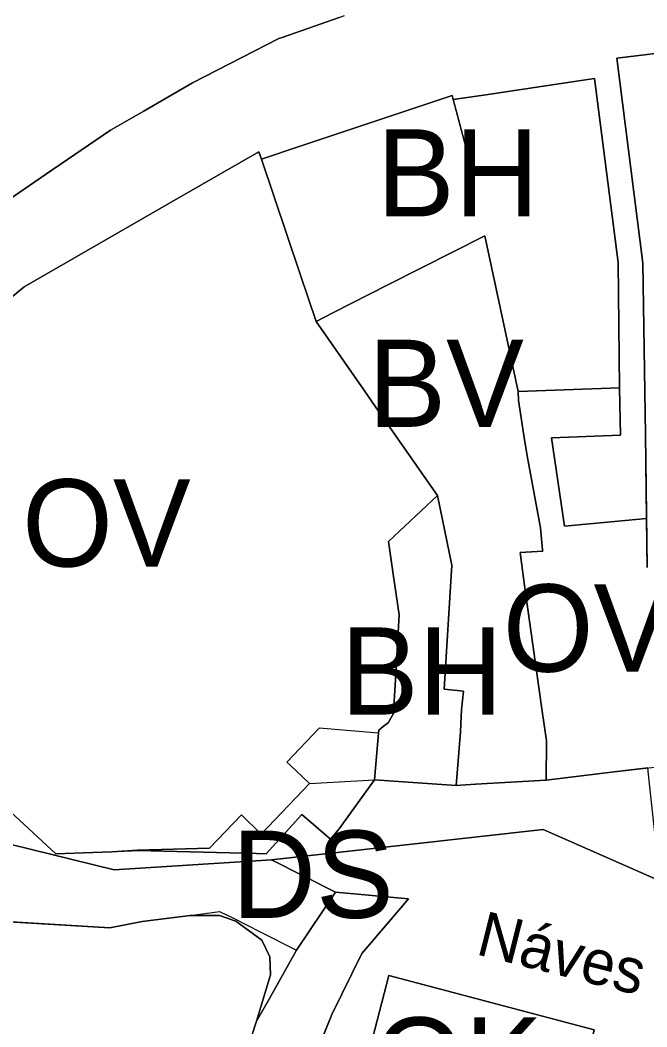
# Model space of a CAD drawing. Extents: x -555509 to -553005, y -1186756 to -1182560.
# Drawn here: x -554552.4 to -554451.9, y -1184542.3 to -1184380.7 of the extents above; entities that cross this region are included whole.
import ezdxf

# ---------------------------------------------------------------- set-up
doc = ezdxf.new("R2010")
doc.units = 0
for name, color, linetype in [('Level 15', 7, 'Continuous'), ('Level 48', 7, 'Continuous'), ('Level 57', 7, 'Continuous'), ('Level 59', 7, 'Continuous'), ('OBRYS_PLOCH', 7, 'Continuous'), ('stav_BV', 7, 'Continuous'), ('stav_DS', 7, 'Continuous'), ('stav_OK', 7, 'Continuous'), ('stav_OV', 7, 'Continuous'), ('stav_PU', 7, 'Continuous'), ('stav_ZP', 7, 'Continuous')]:
    doc.layers.add(name, color=color, linetype=linetype)

msp = doc.modelspace()

# ---------------------------------------------------------------- linework, layer by layer
at = {"layer": 'Level 15'}
for points in [[(-554501.25, -1184380.29), (-554510.4, -1184383.49), (-554510.93, -1184383.67), (-554516.84, -1184386.71), (-554524.77, -1184390.79), (-554532.69, -1184395.37), (-554537.96, -1184398.36), (-554548.38, -1184405.51), (-554555.22, -1184410.2), (-554562.77, -1184415.14), (-554568.86, -1184419.58), (-554572.85, -1184422.48), (-554590.45, -1184437.03), (-554601.65, -1184446.29), (-554608.34, -1184451.84), (-554612.7, -1184455.49), (-554618.09, -1184459.82), (-554614.87, -1184465.98), (-554617.55, -1184467.95), (-554620.8, -1184470.08), (-554622.34, -1184471.17), (-554623.12, -1184469.96), (-554625.1, -1184471.14), (-554624.26, -1184472.46)], [(-554465.07, -1184461.92), (-554451.93, -1184460.67), (-554452.12, -1184447.23), (-554452.51, -1184419.74), (-554456.69, -1184386.82), (-554441.64, -1184385.02)], [(-554555.44, -1184426.5), (-554551.78, -1184423.5), (-554526.46, -1184408.92), (-554526.07, -1184408.7), (-554514.13, -1184401.83), (-554513.72, -1184403.03), (-554507.68, -1184401.01), (-554492.26, -1184395.86), (-554483.13, -1184392.82), (-554482.96, -1184393.47), (-554477.73, -1184392.69), (-554463.86, -1184390.62), (-554460.27, -1184390.08), (-554457.65, -1184410.45), (-554456.48, -1184419.6), (-554456.27, -1184439.75), (-554456.1, -1184447.34), (-554467.17, -1184447.74), (-554465.07, -1184461.92)], [(-554661.22, -1184499.44), (-554615.47, -1184491.83), (-554615.39, -1184490.55), (-554604.27, -1184473.37), (-554583.45, -1184490.21), (-554587.32, -1184496), (-554576.02, -1184502.11), (-554572.02, -1184504.27), (-554564.98, -1184508.08), (-554557.42, -1184512.17), (-554537.36, -1184517.08), (-554512.11, -1184515.49), (-554468.49, -1184510.58), (-554431.8, -1184526.75)], [(-554495.6, -1184502.63), (-554494.94, -1184495.16), (-554504.44, -1184494.32), (-554509.62, -1184499.78), (-554509.18, -1184500.21), (-554506.01, -1184503.24), (-554513.76, -1184511.35), (-554516.89, -1184508.26), (-554522.03, -1184513.6), (-554533.6, -1184513.89), (-554536.89, -1184514.13)], [(-554451.72, -1184500.72), (-554457.1, -1184501.34), (-554457.1, -1184501.34), (-554468.05, -1184502.66), (-554479.39, -1184503.34), (-554482.49, -1184503.52), (-554495.6, -1184502.63), (-554501.22, -1184510.51), (-554502.66, -1184512.16), (-554507.24, -1184508.19), (-554512.95, -1184514.48), (-554514.52, -1184514.44), (-554529.44, -1184514.09), (-554533.44, -1184513.99), (-554536.89, -1184514.13), (-554537.7, -1184514.16), (-554540.78, -1184514.29), (-554546.69, -1184514.53), (-554560.62, -1184501.69)], [(-554622.88, -1184503.76), (-554615.1, -1184503.37), (-554607.58, -1184505.07), (-554591.92, -1184508.62), (-554588.8, -1184510.03), (-554562.63, -1184524.9), (-554538.03, -1184526.36), (-554532.88, -1184525.38), (-554525.17, -1184524.38), (-554520.44, -1184524.39), (-554517.85, -1184525.31), (-554513.65, -1184528.36), (-554512.36, -1184531.03), (-554512.28, -1184533.93), (-554514.53, -1184541.36)], [(-554502.66, -1184512.16), (-554501.22, -1184510.51), (-554495.6, -1184502.63)], [(-554512.11, -1184515.49), (-554537.36, -1184517.08), (-554557.42, -1184512.17), (-554564.98, -1184508.08)], [(-554536.89, -1184514.13), (-554533.44, -1184513.99), (-554529.44, -1184514.09), (-554514.52, -1184514.44), (-554512.95, -1184514.48), (-554507.24, -1184508.19), (-554502.66, -1184512.16)], [(-554431.8, -1184526.75), (-554468.49, -1184510.58), (-554512.11, -1184515.49), (-554501.82, -1184520.64), (-554490.14, -1184521.71), (-554496.01, -1184528.61), (-554497.62, -1184530.51), (-554502.44, -1184540.28), (-554503.73, -1184543.47), (-554500.65, -1184544.34), (-554499.87, -1184544.56), (-554496.29, -1184545.6), (-554493.28, -1184534.02), (-554460.33, -1184542.77), (-554461.09, -1184545.8), (-554464.39, -1184558.17), (-554462.1, -1184559.62), (-554456.48, -1184546.98), (-554454.18, -1184547.62), (-554450.06, -1184548.76)], [(-554514.53, -1184541.36), (-554512.46, -1184537.85), (-554508.08, -1184529.95), (-554501.82, -1184520.64), (-554512.11, -1184515.49)], [(-554501.82, -1184520.64), (-554508.08, -1184529.95), (-554512.46, -1184537.85), (-554514.53, -1184541.36)], [(-554503.73, -1184543.47), (-554502.44, -1184540.28), (-554497.62, -1184530.51), (-554496.01, -1184528.61), (-554490.14, -1184521.71), (-554501.82, -1184520.64)], [(-554514.53, -1184541.36), (-554523.93, -1184570.22), (-554534.86, -1184570.77), (-554558.65, -1184573.59), (-554586.8, -1184578.55), (-554589.05, -1184575.07)]]:
    msp.add_lwpolyline(points, dxfattribs=at)
at = {"layer": 'Level 48'}
for p, q in [((-554457.65, -1184410.45), (-554460.27, -1184390.08)), ((-554479.61, -1184406.08), (-554483.13, -1184392.82)), ((-554482.96, -1184393.47), (-554479.61, -1184406.08)), ((-554513.72, -1184403.03), (-554507.5, -1184421.48)), ((-554493.34, -1184423.13), (-554477.89, -1184415.35)), ((-554477.89, -1184415.35), (-554472.51, -1184440.32)), ((-554507.5, -1184421.48), (-554504.94, -1184429.06)), ((-554502.26, -1184427.69), (-554493.34, -1184423.13)), ((-554504.94, -1184429.06), (-554502.26, -1184427.69)), ((-554472.51, -1184440.32), (-554456.27, -1184439.75)), ((-554494.94, -1184495.16), (-554495.6, -1184502.63)), ((-554495.6, -1184502.63), (-554482.49, -1184503.52))]:
    msp.add_line(p, q, dxfattribs=at)
for points in [[(-554460.27, -1184390.08), (-554463.86, -1184390.62), (-554477.73, -1184392.69), (-554482.96, -1184393.47)], [(-554483.13, -1184392.82), (-554492.26, -1184395.86), (-554507.68, -1184401.01), (-554513.72, -1184403.03)], [(-554456.27, -1184439.75), (-554456.48, -1184419.6), (-554457.65, -1184410.45)], [(-554485.48, -1184457), (-554493.34, -1184464.37), (-554492.58, -1184469.63), (-554491.64, -1184476.13), (-554491.8, -1184478.94), (-554492.17, -1184485.75)], [(-554481.62, -1184491.37), (-554481.28, -1184488.38), (-554484.42, -1184488.1), (-554483.16, -1184468.16), (-554485.48, -1184457)], [(-554492.17, -1184485.75), (-554492.36, -1184489.12), (-554492.52, -1184491.97), (-554493.38, -1184493.48), (-554494.16, -1184494.08), (-554494.9, -1184494.65), (-554494.94, -1184495.16)], [(-554482.49, -1184503.52), (-554481.8, -1184494.9), (-554481.69, -1184492.44), (-554481.62, -1184491.37)]]:
    msp.add_lwpolyline(points, dxfattribs=at)
at = {"layer": 'OBRYS_PLOCH'}
for p, q in [((-554510.4, -1184383.49), (-554501.25, -1184380.29)), ((-554510.93, -1184383.67), (-554510.4, -1184383.49)), ((-554457.65, -1184410.45), (-554460.27, -1184390.08)), ((-554479.61, -1184406.08), (-554483.13, -1184392.82)), ((-554482.96, -1184393.47), (-554479.61, -1184406.08)), ((-554537.96, -1184398.36), (-554532.69, -1184395.37)), ((-554548.38, -1184405.51), (-554537.96, -1184398.36)), ((-554513.72, -1184403.03), (-554507.5, -1184421.48)), ((-554477.89, -1184415.35), (-554493.34, -1184423.13)), ((-554493.34, -1184423.13), (-554477.89, -1184415.35)), ((-554472.51, -1184440.32), (-554477.89, -1184415.35)), ((-554477.89, -1184415.35), (-554472.51, -1184440.32)), ((-554507.5, -1184421.48), (-554504.94, -1184429.06)), ((-554493.34, -1184423.13), (-554502.26, -1184427.69)), ((-554502.26, -1184427.69), (-554493.34, -1184423.13)), ((-554502.26, -1184427.69), (-554504.94, -1184429.06)), ((-554504.94, -1184429.06), (-554502.26, -1184427.69)), ((-554456.27, -1184439.75), (-554472.51, -1184440.32)), ((-554472.51, -1184440.32), (-554456.27, -1184439.75)), ((-554472.51, -1184440.32), (-554472.48, -1184441.75)), ((-554472.48, -1184441.75), (-554472.51, -1184440.32)), ((-554472.48, -1184441.75), (-554471.55, -1184447.68)), ((-554471.55, -1184447.68), (-554472.48, -1184441.75)), ((-554471.55, -1184447.68), (-554471.08, -1184450.66)), ((-554471.08, -1184450.66), (-554471.55, -1184447.68)), ((-554465.07, -1184461.92), (-554467.17, -1184447.74)), ((-554471.08, -1184450.66), (-554468.93, -1184462.21)), ((-554468.93, -1184462.21), (-554471.08, -1184450.66)), ((-554451.93, -1184460.67), (-554465.07, -1184461.92)), ((-554451.82, -1184468.57), (-554451.93, -1184460.67)), ((-554468.93, -1184462.21), (-554468.63, -1184465.74)), ((-554468.63, -1184465.74), (-554468.93, -1184462.21)), ((-554495.6, -1184502.63), (-554494.94, -1184495.16)), ((-554494.94, -1184495.16), (-554495.6, -1184502.63)), ((-554506.01, -1184503.24), (-554495.6, -1184502.63)), ((-554495.6, -1184502.63), (-554482.49, -1184503.52)), ((-554537.36, -1184517.08), (-554557.42, -1184512.17)), ((-554512.11, -1184515.49), (-554537.36, -1184517.08)), ((-554501.82, -1184520.64), (-554512.11, -1184515.49)), ((-554501.82, -1184520.64), (-554501.82, -1184520.64)), ((-554562.63, -1184524.9), (-554538.03, -1184526.36)), ((-554525.17, -1184524.38), (-554520.43, -1184523.77)), ((-554525.17, -1184524.38), (-554525.17, -1184524.38)), ((-554520.43, -1184523.77), (-554518.09, -1184524.86)), ((-554518.09, -1184524.86), (-554513.9, -1184527.03)), ((-554513.9, -1184527.03), (-554508.08, -1184529.95)), ((-554502.44, -1184540.28), (-554497.62, -1184530.51)), ((-554512.46, -1184537.85), (-554514.53, -1184541.36)), ((-554503.73, -1184543.47), (-554502.44, -1184540.28)), ((-554514.53, -1184541.36), (-554523.93, -1184570.22))]:
    msp.add_line(p, q, dxfattribs=at)
for points in [[(-554532.69, -1184395.37), (-554524.77, -1184390.79), (-554516.84, -1184386.71), (-554510.93, -1184383.67)], [(-554441.64, -1184385.02), (-554456.69, -1184386.82), (-554452.51, -1184419.74), (-554452.12, -1184447.23), (-554451.82, -1184468.57)], [(-554460.27, -1184390.08), (-554463.86, -1184390.62), (-554477.73, -1184392.69), (-554482.96, -1184393.47)], [(-554483.13, -1184392.82), (-554492.26, -1184395.86), (-554507.68, -1184401.01), (-554513.72, -1184403.03)], [(-554494.94, -1184495.16), (-554494.9, -1184494.65), (-554494.16, -1184494.08), (-554493.38, -1184493.48), (-554492.52, -1184491.97), (-554492.36, -1184489.12), (-554492.17, -1184485.75), (-554491.8, -1184478.94), (-554491.64, -1184476.13), (-554492.58, -1184469.63), (-554493.34, -1184464.37), (-554485.48, -1184457), (-554485.74, -1184456.63), (-554495.39, -1184442.77), (-554497.29, -1184440.04), (-554504.94, -1184429.06), (-554507.5, -1184421.48), (-554513.72, -1184403.03), (-554514.13, -1184401.83), (-554526.07, -1184408.7), (-554526.46, -1184408.92), (-554551.78, -1184423.5), (-554555.44, -1184426.5)], [(-554562.77, -1184415.14), (-554555.22, -1184410.2), (-554548.38, -1184405.51)], [(-554456.27, -1184439.75), (-554456.48, -1184419.6), (-554457.65, -1184410.45)], [(-554504.94, -1184429.06), (-554497.29, -1184440.04), (-554495.39, -1184442.77), (-554485.74, -1184456.63), (-554485.48, -1184457), (-554483.16, -1184468.16), (-554484.42, -1184488.1), (-554481.28, -1184488.38), (-554481.62, -1184491.37)], [(-554467.17, -1184447.74), (-554456.1, -1184447.34), (-554456.27, -1184439.75)], [(-554485.48, -1184457), (-554493.34, -1184464.37), (-554492.58, -1184469.63), (-554491.64, -1184476.13), (-554491.8, -1184478.94), (-554492.17, -1184485.75)], [(-554481.62, -1184491.37), (-554481.28, -1184488.38), (-554484.42, -1184488.1), (-554483.16, -1184468.16), (-554485.48, -1184457)], [(-554468.63, -1184465.74), (-554468.55, -1184465.93), (-554472.2, -1184466.16), (-554471.52, -1184471.45), (-554468.72, -1184491.22)], [(-554468.72, -1184491.22), (-554471.52, -1184471.45), (-554472.2, -1184466.16), (-554468.55, -1184465.93), (-554468.63, -1184465.74)], [(-554492.17, -1184485.75), (-554492.36, -1184489.12), (-554492.52, -1184491.97), (-554493.38, -1184493.48), (-554494.16, -1184494.08), (-554494.9, -1184494.65), (-554494.94, -1184495.16)], [(-554481.62, -1184491.37), (-554481.69, -1184492.44), (-554481.8, -1184494.9), (-554482.49, -1184503.52)], [(-554482.49, -1184503.52), (-554481.8, -1184494.9), (-554481.69, -1184492.44), (-554481.62, -1184491.37)], [(-554468.72, -1184491.22), (-554468, -1184496.38), (-554468.05, -1184502.66)], [(-554468.05, -1184502.66), (-554468, -1184496.38), (-554468.72, -1184491.22)], [(-554468.05, -1184502.66), (-554457.1, -1184501.34), (-554439.89, -1184499.37)], [(-554560.62, -1184501.69), (-554546.69, -1184514.53), (-554540.78, -1184514.29), (-554537.7, -1184514.16), (-554536.89, -1184514.13), (-554533.6, -1184513.89), (-554522.03, -1184513.6), (-554516.89, -1184508.26), (-554513.76, -1184511.35), (-554506.01, -1184503.24)], [(-554589.05, -1184575.07), (-554586.8, -1184578.55), (-554558.65, -1184573.59), (-554534.86, -1184570.77), (-554523.93, -1184570.22), (-554514.53, -1184541.36), (-554512.28, -1184533.93), (-554512.36, -1184531.03), (-554513.65, -1184528.36), (-554517.85, -1184525.31), (-554520.44, -1184524.39), (-554525.17, -1184524.38), (-554532.88, -1184525.38), (-554538.03, -1184526.36), (-554562.63, -1184524.9), (-554588.8, -1184510.03), (-554591.92, -1184508.62), (-554607.58, -1184505.07), (-554615.1, -1184503.37), (-554622.88, -1184503.76)], [(-554482.49, -1184503.52), (-554479.39, -1184503.34), (-554468.05, -1184502.66)], [(-554497.62, -1184530.51), (-554496.01, -1184528.61), (-554490.14, -1184521.71), (-554501.82, -1184520.64)], [(-554538.03, -1184526.36), (-554532.88, -1184525.38), (-554525.17, -1184524.38)], [(-554508.08, -1184529.95), (-554512.46, -1184537.85)]]:
    msp.add_lwpolyline(points, dxfattribs=at)
msp.add_lwpolyline([(-554490.82, -1184563.58), (-554486.05, -1184560.65), (-554484.65, -1184558.85), (-554470.11, -1184562.71), (-554469.92, -1184562.02), (-554469.15, -1184562.23), (-554468.04, -1184558.05), (-554468.82, -1184557.84), (-554468.61, -1184557.07), (-554464.39, -1184558.17), (-554461.09, -1184545.8), (-554460.33, -1184542.77), (-554493.28, -1184534.02), (-554496.29, -1184545.6), (-554499.87, -1184544.56), (-554500.65, -1184544.34), (-554501.53, -1184547.4), (-554501.31, -1184547.46), (-554502.51, -1184549.89), (-554505.11, -1184548.62), (-554508.55, -1184556.13), (-554503.03, -1184558.71)], close=True, dxfattribs=at)
at = {"layer": 'stav_BV'}
for p, q in [((-554516.84, -1184386.71), (-554510.93, -1184383.67)), ((-554477.89, -1184415.35), (-554493.34, -1184423.13)), ((-554472.51, -1184440.32), (-554477.89, -1184415.35)), ((-554493.34, -1184423.13), (-554502.26, -1184427.69)), ((-554502.26, -1184427.69), (-554504.94, -1184429.06)), ((-554472.48, -1184441.75), (-554472.51, -1184440.32)), ((-554471.55, -1184447.68), (-554472.48, -1184441.75)), ((-554471.08, -1184450.66), (-554471.55, -1184447.68)), ((-554468.93, -1184462.21), (-554471.08, -1184450.66)), ((-554468.63, -1184465.74), (-554468.93, -1184462.21))]:
    msp.add_line(p, q, dxfattribs=at)
for points in [[(-554510.93, -1184383.67), (-554510.4, -1184383.49), (-554501.25, -1184380.29), (-554500.4, -1184379.99)], [(-554441.64, -1184385.02), (-554456.69, -1184386.82), (-554452.51, -1184419.74), (-554452.12, -1184447.23), (-554451.82, -1184468.57)], [(-554532.69, -1184395.37), (-554524.77, -1184390.79), (-554516.84, -1184386.71)], [(-554555.22, -1184410.2), (-554548.38, -1184405.51), (-554537.96, -1184398.36), (-554532.69, -1184395.37)], [(-554504.94, -1184429.06), (-554497.29, -1184440.04), (-554495.39, -1184442.77), (-554485.74, -1184456.63), (-554485.48, -1184457), (-554483.16, -1184468.16), (-554484.42, -1184488.1), (-554481.28, -1184488.38), (-554481.62, -1184491.37)], [(-554468.72, -1184491.22), (-554471.52, -1184471.45), (-554472.2, -1184466.16), (-554468.55, -1184465.93), (-554468.63, -1184465.74)], [(-554481.62, -1184491.37), (-554481.69, -1184492.44), (-554481.8, -1184494.9), (-554482.49, -1184503.52)], [(-554468.05, -1184502.66), (-554468, -1184496.38), (-554468.72, -1184491.22)], [(-554482.49, -1184503.52), (-554479.39, -1184503.34), (-554468.05, -1184502.66)]]:
    msp.add_lwpolyline(points, dxfattribs=at)
at = {"layer": 'stav_DS'}
for p, q in [((-554537.36, -1184517.08), (-554557.42, -1184512.17)), ((-554512.11, -1184515.49), (-554537.36, -1184517.08)), ((-554501.82, -1184520.64), (-554512.11, -1184515.49)), ((-554490.14, -1184521.71), (-554501.82, -1184520.64)), ((-554496.01, -1184528.61), (-554490.14, -1184521.71)), ((-554525.17, -1184524.38), (-554520.43, -1184523.77)), ((-554520.43, -1184523.77), (-554518.09, -1184524.86)), ((-554518.09, -1184524.86), (-554513.9, -1184527.03)), ((-554513.9, -1184527.03), (-554508.08, -1184529.95)), ((-554497.62, -1184530.51), (-554496.01, -1184528.61)), ((-554508.08, -1184529.95), (-554512.46, -1184537.85)), ((-554502.44, -1184540.28), (-554497.62, -1184530.51)), ((-554512.46, -1184537.85), (-554514.53, -1184541.36)), ((-554505.72, -1184548.39), (-554502.44, -1184540.28))]:
    msp.add_line(p, q, dxfattribs=at)
for points in [[(-554588.8, -1184510.03), (-554562.63, -1184524.9), (-554538.03, -1184526.36), (-554532.88, -1184525.38), (-554525.17, -1184524.38), (-554525.17, -1184524.38)], [(-554514.53, -1184541.36), (-554523.93, -1184570.22), (-554523.93, -1184570.22)]]:
    msp.add_lwpolyline(points, dxfattribs=at)
at = {"layer": 'stav_OK'}
msp.add_lwpolyline([(-554490.82, -1184563.58), (-554486.05, -1184560.65), (-554484.65, -1184558.85), (-554470.11, -1184562.71), (-554469.92, -1184562.02), (-554469.15, -1184562.23), (-554468.04, -1184558.05), (-554468.82, -1184557.84), (-554468.61, -1184557.07), (-554464.39, -1184558.17), (-554461.09, -1184545.8), (-554460.33, -1184542.77), (-554493.28, -1184534.02), (-554496.29, -1184545.6), (-554499.87, -1184544.56), (-554500.65, -1184544.34), (-554501.53, -1184547.4), (-554501.31, -1184547.46), (-554502.51, -1184549.89), (-554505.11, -1184548.62), (-554508.55, -1184556.13), (-554503.03, -1184558.71)], close=True, dxfattribs=at)
at = {"layer": 'stav_OV'}
for p, q in [((-554456.27, -1184439.75), (-554472.51, -1184440.32)), ((-554472.51, -1184440.32), (-554472.48, -1184441.75)), ((-554472.48, -1184441.75), (-554471.55, -1184447.68)), ((-554471.55, -1184447.68), (-554471.08, -1184450.66)), ((-554465.07, -1184461.92), (-554467.17, -1184447.74)), ((-554471.08, -1184450.66), (-554468.93, -1184462.21)), ((-554451.93, -1184460.67), (-554465.07, -1184461.92)), ((-554451.82, -1184468.57), (-554451.93, -1184460.67)), ((-554468.93, -1184462.21), (-554468.63, -1184465.74)), ((-554495.6, -1184502.63), (-554494.94, -1184495.16)), ((-554506.01, -1184503.24), (-554495.6, -1184502.63))]:
    msp.add_line(p, q, dxfattribs=at)
for points in [[(-554494.94, -1184495.16), (-554494.9, -1184494.65), (-554494.16, -1184494.08), (-554493.38, -1184493.48), (-554492.52, -1184491.97), (-554492.36, -1184489.12), (-554492.17, -1184485.75), (-554491.8, -1184478.94), (-554491.64, -1184476.13), (-554492.58, -1184469.63), (-554493.34, -1184464.37), (-554485.48, -1184457), (-554485.74, -1184456.63), (-554495.39, -1184442.77), (-554497.29, -1184440.04), (-554504.94, -1184429.06), (-554507.5, -1184421.48), (-554513.72, -1184403.03), (-554514.13, -1184401.83), (-554526.07, -1184408.7), (-554526.46, -1184408.92), (-554551.78, -1184423.5), (-554555.44, -1184426.5)], [(-554467.17, -1184447.74), (-554456.1, -1184447.34), (-554456.27, -1184439.75)], [(-554468.63, -1184465.74), (-554468.55, -1184465.93), (-554472.2, -1184466.16), (-554471.52, -1184471.45), (-554468.72, -1184491.22)], [(-554468.72, -1184491.22), (-554468, -1184496.38), (-554468.05, -1184502.66)], [(-554468.05, -1184502.66), (-554457.1, -1184501.34), (-554439.89, -1184499.37)], [(-554560.62, -1184501.69), (-554546.69, -1184514.53), (-554540.78, -1184514.29), (-554537.7, -1184514.16), (-554536.89, -1184514.13), (-554533.6, -1184513.89), (-554522.03, -1184513.6), (-554516.89, -1184508.26), (-554513.76, -1184511.35), (-554506.01, -1184503.24)]]:
    msp.add_lwpolyline(points, dxfattribs=at)
at = {"layer": 'stav_PU'}
msp.add_line((-554536.89, -1184514.13), (-554537.7, -1184514.16), dxfattribs=at)
for points in [[(-554465.07, -1184461.92), (-554451.93, -1184460.67), (-554452.12, -1184447.23), (-554452.51, -1184419.74), (-554456.69, -1184386.82), (-554441.64, -1184385.02), (-554430.51, -1184383.75), (-554426.68, -1184384.53), (-554422.04, -1184384.43), (-554409.92, -1184382.67), (-554405.27, -1184382.19), (-554371.6, -1184378.73), (-554370.82, -1184378.65), (-554369.93, -1184381.01)], [(-554501.25, -1184380.29), (-554510.4, -1184383.49), (-554510.93, -1184383.67), (-554516.84, -1184386.71), (-554524.77, -1184390.79), (-554532.69, -1184395.37), (-554537.96, -1184398.36), (-554548.38, -1184405.51), (-554555.22, -1184410.2), (-554562.77, -1184415.14), (-554568.86, -1184419.58), (-554572.85, -1184422.48), (-554590.45, -1184437.03), (-554601.65, -1184446.29), (-554608.34, -1184451.84), (-554612.7, -1184455.49), (-554618.09, -1184459.82), (-554614.87, -1184465.98), (-554617.55, -1184467.95), (-554620.8, -1184470.08), (-554622.34, -1184471.17), (-554623.12, -1184469.96), (-554625.1, -1184471.14), (-554624.26, -1184472.46)], [(-554555.44, -1184426.5), (-554551.78, -1184423.5), (-554526.46, -1184408.92), (-554526.07, -1184408.7), (-554514.13, -1184401.83), (-554513.72, -1184403.03), (-554507.68, -1184401.01), (-554492.26, -1184395.86), (-554483.13, -1184392.82), (-554482.96, -1184393.47), (-554477.73, -1184392.69), (-554463.86, -1184390.62), (-554460.27, -1184390.08), (-554457.65, -1184410.45), (-554456.48, -1184419.6), (-554456.27, -1184439.75), (-554456.1, -1184447.34), (-554467.17, -1184447.74), (-554465.07, -1184461.92)], [(-554495.6, -1184502.63), (-554494.94, -1184495.16), (-554504.44, -1184494.32), (-554509.62, -1184499.78), (-554509.18, -1184500.21), (-554506.01, -1184503.24), (-554513.76, -1184511.35), (-554516.89, -1184508.26), (-554522.03, -1184513.6), (-554533.6, -1184513.89), (-554536.89, -1184514.13)], [(-554411.1, -1184515.83), (-554425.44, -1184516.97), (-554425.06, -1184512.13), (-554425.04, -1184511.26), (-554427.96, -1184511.38), (-554428.02, -1184512.22), (-554432.41, -1184512.42), (-554432.45, -1184517.93), (-554438.27, -1184517.89), (-554438.57, -1184515.33), (-554450.43, -1184512.58), (-554451.39, -1184503.77), (-554451.72, -1184500.72), (-554457.1, -1184501.34), (-554468.05, -1184502.66), (-554479.39, -1184503.34), (-554482.49, -1184503.52), (-554495.6, -1184502.63)], [(-554537.7, -1184514.16), (-554540.78, -1184514.29), (-554546.69, -1184514.53), (-554560.62, -1184501.69)], [(-554622.88, -1184503.76), (-554615.1, -1184503.37), (-554607.58, -1184505.07), (-554591.92, -1184508.62), (-554588.8, -1184510.03), (-554562.63, -1184524.9), (-554538.03, -1184526.36), (-554532.88, -1184525.38), (-554525.17, -1184524.38), (-554520.44, -1184524.39), (-554517.85, -1184525.31), (-554513.65, -1184528.36), (-554512.36, -1184531.03), (-554512.28, -1184533.93), (-554514.53, -1184541.36)], [(-554499.87, -1184544.56), (-554496.29, -1184545.6), (-554493.28, -1184534.02), (-554460.33, -1184542.77), (-554461.09, -1184545.8), (-554464.39, -1184558.17)], [(-554514.53, -1184541.36), (-554523.93, -1184570.22), (-554534.86, -1184570.77), (-554558.65, -1184573.59), (-554586.8, -1184578.55), (-554589.05, -1184575.07)]]:
    msp.add_lwpolyline(points, dxfattribs=at)
at = {"layer": 'stav_ZP'}
msp.add_lwpolyline([(-554589.05, -1184575.07), (-554586.8, -1184578.55), (-554558.65, -1184573.59), (-554534.86, -1184570.77), (-554523.93, -1184570.22), (-554514.53, -1184541.36), (-554512.28, -1184533.93), (-554512.36, -1184531.03), (-554513.65, -1184528.36), (-554517.85, -1184525.31), (-554520.44, -1184524.39), (-554525.17, -1184524.38), (-554532.88, -1184525.38), (-554538.03, -1184526.36), (-554562.63, -1184524.9), (-554588.8, -1184510.03), (-554591.92, -1184508.62), (-554607.58, -1184505.07), (-554615.1, -1184503.37), (-554622.88, -1184503.76)], dxfattribs=at)

# ---------------------------------------------------------------- texts
at = {"layer": 'Level 57'}
msp.add_text('Náves', height=7.174, rotation=345.808, dxfattribs=at).set_placement((-554479.51, -1184530.57))
at = {"layer": 'Level 59'}
for s, p in [('BH', (-554495.21, -1184412.23)), ('BV', (-554496.58, -1184445.99)), ('OV', (-554552.11, -1184468.4)), ('OV', (-554474.99, -1184485.27)), ('BH', (-554500.99, -1184492.16)), ('DS', (-554518.48, -1184524.78)), ('OK', (-554495.68, -1184554.76))]:
    msp.add_text(s, height=14, dxfattribs=at).set_placement(p)

doc.saveas('drawing.dxf')
